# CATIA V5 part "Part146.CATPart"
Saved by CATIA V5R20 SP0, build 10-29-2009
Part number: IA 5717SF
Revision: ANY
Definition: UNKNOWN
Nomenclature: IA 5717SF
Source: Unknown
Bounding box of the stored display mesh (mm): x -2.85 to 2.85, y -7.925 to 9.045, z -2.711 to 2.711
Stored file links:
  C:\Users\Utente\Desktop\IO LAVORO\3D X SITO CF\CUMSA\3D files FA\FA 105706-20\Part146.CATPart

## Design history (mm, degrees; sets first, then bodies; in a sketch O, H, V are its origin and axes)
Body1 "Cortar-Extruir2" (main body)
  Solid1: solid without history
